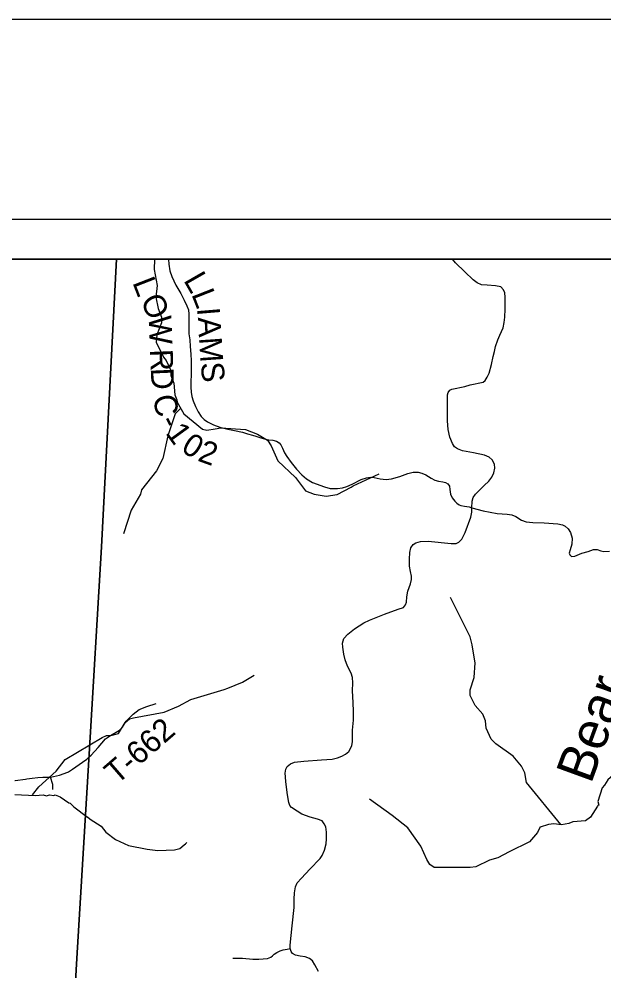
# Model space of a CAD drawing. Extents: x -1.8 to 75.7, y -2 to 25.
# Drawn here: x 6.244 to 7.704, y 19.123 to 21.5 of the extents above; entities that cross this region are included whole.
import ezdxf

# ---------------------------------------------------------------- set-up
doc = ezdxf.new("R2010")
doc.units = 0
for name, color, linetype in [('GM_X_County_Road', 7, 'Continuous'), ('GM_X_County_Road_Text', 7, 'Continuous'), ('GM_X_Minor_River', 7, 'Continuous'), ('GM_X_Minor_River_Text', 7, 'Continuous'), ('GM_X_Township', 7, 'Continuous'), ('GM_X_Township_Road', 7, 'Continuous'), ('GM_X_Township_Road_Text', 7, 'Continuous'), ('GM_X_Township_ROW', 7, 'Continuous'), ('SH_Border', 7, 'Continuous'), ('SH_Data', 7, 'Continuous')]:
    doc.layers.add(name, color=color, linetype=linetype)

msp = doc.modelspace()

# ---------------------------------------------------------------- linework, layer by layer
at = {"layer": 'GM_X_County_Road'}
for points in [[(6.6168, 20.9), (6.6167, 20.8997), (6.6179, 20.8877), (6.6203, 20.8713), (6.6251, 20.8569), (6.6355, 20.8357), (6.6479, 20.8148), (6.6564, 20.7979), (6.6629, 20.7838), (6.6669, 20.7736), (6.668, 20.7626), (6.668, 20.7455), (6.6676, 20.729), (6.6678, 20.7155), (6.668, 20.714)], [(6.9919, 19.1211), (6.9826, 19.1385), (6.9769, 19.148), (6.9692, 19.1539), (6.9581, 19.1577), (6.9457, 19.1598), (6.9339, 19.1623), (6.9264, 19.1668), (6.923, 19.1716), (6.9205, 19.1792), (6.9208, 19.1872), (6.9257, 19.2354), (6.9305, 19.2814), (6.9309, 19.3024), (6.9316, 19.3178), (6.9339, 19.3332), (6.9386, 19.3432), (6.9491, 19.3547), (6.9699, 19.3767), (6.9955, 19.4036), (7.0011, 19.4115), (7.0066, 19.4247), (7.0104, 19.4403), (7.0116, 19.4528), (7.0118, 19.4691), (7.01, 19.4824), (7.0059, 19.4906), (7.0007, 19.4974), (6.9887, 19.5021), (6.9706, 19.5069), (6.95, 19.5146), (6.938, 19.522), (6.9244, 19.5309), (6.9201, 19.5363), (6.9178, 19.5435), (6.9144, 19.5623), (6.9099, 19.5949), (6.909, 19.6074), (6.9083, 19.6169), (6.9098, 19.6266), (6.9135, 19.6334), (6.9217, 19.6398), (6.9319, 19.6443), (6.9547, 19.6466), (6.9989, 19.6504), (7.026, 19.652), (7.0389, 19.6554), (7.0496, 19.6592), (7.0591, 19.6642), (7.067, 19.6706), (7.0706, 19.6764), (7.0747, 19.6857), (7.0763, 19.6952), (7.0768, 19.7054), (7.0768, 19.7244), (7.0786, 19.7489), (7.0788, 19.7704), (7.0777, 19.793), (7.0765, 19.8227), (7.0774, 19.8424), (7.0763, 19.8555), (7.0731, 19.8664), (7.0641, 19.8838), (7.0582, 19.8995), (7.0546, 19.9137), (7.0523, 19.9312), (7.0516, 19.9416), (7.0548, 19.9527), (7.0645, 19.964), (7.0817, 19.9771), (7.1048, 19.9921), (7.1193, 19.9991), (7.1567, 20.0136), (7.1904, 20.0267), (7.204, 20.0306), (7.2088, 20.0369), (7.211, 20.0441), (7.2122, 20.057), (7.2146, 20.0713), (7.2212, 20.0899), (7.2237, 20.1005), (7.2237, 20.1089), (7.2214, 20.1207), (7.2192, 20.1338), (7.2187, 20.1508), (7.2194, 20.1682), (7.2221, 20.1793), (7.228, 20.1881), (7.235, 20.192), (7.2461, 20.1952), (7.2658, 20.1961), (7.3229, 20.1899), (7.3355, 20.1904), (7.3423, 20.1938), (7.3491, 20.2013), (7.3578, 20.218), (7.3723, 20.2563), (7.3745, 20.2682), (7.3743, 20.2791), (7.3755, 20.2959), (7.3779, 20.3051), (7.3833, 20.3131), (7.3915, 20.3211), (7.4053, 20.3347), (7.4167, 20.3458), (7.4245, 20.3558), (7.4298, 20.3665), (7.432, 20.3783), (7.4308, 20.388), (7.4254, 20.3991), (7.4177, 20.4062), (7.4063, 20.4108), (7.3786, 20.4169), (7.3512, 20.4218), (7.3386, 20.4266), (7.3309, 20.4319), (7.3263, 20.4399), (7.3195, 20.4562), (7.3151, 20.4749), (7.3141, 20.4962), (7.3134, 20.5297), (7.3134, 20.5525), (7.3134, 20.5617), (7.3156, 20.5675), (7.3195, 20.5731), (7.3243, 20.5753), (7.3566, 20.5821), (7.3702, 20.5867), (7.4031, 20.593), (7.408, 20.5971), (7.4131, 20.6054), (7.4179, 20.616), (7.4233, 20.6369), (7.4281, 20.657), (7.431, 20.6701), (7.4339, 20.682), (7.4395, 20.699), (7.4446, 20.7104), (7.4529, 20.7291), (7.4555, 20.7419), (7.4572, 20.7557), (7.4575, 20.7754), (7.4575, 20.8052), (7.4565, 20.8166), (7.4534, 20.8239), (7.4468, 20.8309), (7.4339, 20.8336), (7.4131, 20.8353), (7.3985, 20.8365), (7.3874, 20.8414), (7.3774, 20.8484), (7.3568, 20.869), (7.3335, 20.8908), (7.3261, 20.9)], [(6.668, 20.714), (6.6702, 20.6987), (6.6714, 20.682), (6.673, 20.6631), (6.6737, 20.6461), (6.6739, 20.6272), (6.6735, 20.6117), (6.6725, 20.5947), (6.6725, 20.5805), (6.6737, 20.5685), (6.6756, 20.5576), (6.6789, 20.5465), (6.6843, 20.5321), (6.6909, 20.5191), (6.6983, 20.5076), (6.7063, 20.5), (6.7145, 20.4944), (6.7294, 20.4866), (6.745, 20.4809), (6.7648, 20.476), (6.7818, 20.4727), (6.8019, 20.4679), (6.8146, 20.4644), (6.8271, 20.4611), (6.8354, 20.4585), (6.8479, 20.4538), (6.8594, 20.4507), (6.8675, 20.4491), (6.8779, 20.4486), (6.8864, 20.4462), (6.8932, 20.4415), (6.8974, 20.4365), (6.9017, 20.4285), (6.9069, 20.417), (6.9121, 20.4078), (6.9236, 20.3927), (6.9366, 20.3759), (6.9496, 20.3615), (6.9619, 20.3514), (6.9763, 20.3426), (7.0065, 20.3318), (7.0209, 20.3278), (7.0388, 20.3275), (7.0513, 20.3294), (7.0626, 20.3329), (7.0754, 20.3381), (7.0985, 20.3497), (7.1113, 20.3544), (7.1214, 20.3558), (7.1306, 20.3554), (7.1457, 20.3518), (7.1608, 20.3499), (7.1738, 20.3514), (7.1948, 20.358), (7.2149, 20.365), (7.2281, 20.3686), (7.2406, 20.3681), (7.2496, 20.366), (7.2592, 20.3617), (7.2727, 20.3532), (7.2821, 20.3483), (7.2909, 20.3457), (7.3019, 20.3445), (7.3088, 20.3429), (7.3147, 20.3391), (7.3185, 20.3334), (7.3196, 20.3249), (7.3211, 20.3134), (7.3253, 20.3046), (7.3316, 20.2961), (7.3369, 20.2908), (7.3432, 20.2869), (7.3471, 20.2852), (7.3563, 20.2835), (7.3677, 20.2818), (7.3743, 20.2791)]]:
    msp.add_lwpolyline(points, dxfattribs=at)
at = {"layer": 'GM_X_Minor_River'}
for points in [[(6.5816, 20.9), (6.5809, 20.8746), (6.5884, 20.8345), (6.5849, 20.8058), (6.5915, 20.7771), (6.5992, 20.7556), (6.5995, 20.7415), (6.5877, 20.7115), (6.586, 20.693), (6.6041, 20.6556), (6.611, 20.6474), (6.6228, 20.6219), (6.6228, 20.6098), (6.6301, 20.5905), (6.633, 20.5616), (6.6379, 20.5493), (6.6389, 20.5432), (6.655, 20.5142), (6.7015, 20.4762), (6.7128, 20.4736), (6.7336, 20.4764), (6.7473, 20.479), (6.8096, 20.4751), (6.8394, 20.4631), (6.8643, 20.4483), (6.8737, 20.4343), (6.89, 20.3969), (6.9344, 20.3549), (6.9591, 20.3214), (6.9804, 20.3132), (7.0109, 20.3088), (7.0382, 20.3124), (7.0728, 20.3311), (7.0782, 20.3343), (7.143, 20.3642)], [(6.6459, 20.5266), (6.6335, 20.5145), (6.6152, 20.4589), (6.6029, 20.4027), (6.5868, 20.3721), (6.5491, 20.3243), (6.5469, 20.3137), (6.5241, 20.2731), (6.5042, 20.2141)], [(7.5964, 19.4888), (7.5111, 19.5937), (7.5069, 19.6178), (7.4984, 19.6344), (7.4776, 19.659), (7.4343, 19.69), (7.4229, 19.7017), (7.4101, 19.7295), (7.4084, 19.7474), (7.4018, 19.7643), (7.3827, 19.7858), (7.3703, 19.8105), (7.3703, 19.8249), (7.3799, 19.8554), (7.3829, 19.8921), (7.3772, 19.9268), (7.3749, 19.9372), (7.3706, 19.9574), (7.3246, 20.0489), (7.3214, 20.0555)], [(6.2774, 19.5626), (6.2934, 19.5824), (6.3362, 19.6221), (6.359, 19.651), (6.4514, 19.7061), (6.4621, 19.7111), (6.473, 19.7108), (6.4917, 19.7162), (6.5088, 19.743), (6.5197, 19.7522), (6.5292, 19.7549), (6.606, 19.7692), (6.642, 19.7844), (6.6731, 19.8008), (6.7559, 19.8259), (6.765, 19.829), (6.8018, 19.8438), (6.831, 19.8611)], [(7.7329, 19.6164), (7.714, 19.6003), (7.7057, 19.5866), (7.6996, 19.5805), (7.6894, 19.5463), (7.6913, 19.5368), (7.6891, 19.5364), (7.6887, 19.5345), (7.6706, 19.5071), (7.6585, 19.498), (7.6264, 19.4952), (7.6169, 19.491), (7.5984, 19.4876), (7.5791, 19.4906), (7.5663, 19.4886), (7.5447, 19.4821)], [(6.2333, 19.5631), (6.2843, 19.5613), (6.3043, 19.5625), (6.3123, 19.5599), (6.3195, 19.5629), (6.3308, 19.5607), (6.3338, 19.5626), (6.3463, 19.5577), (6.3682, 19.5429), (6.3716, 19.5421), (6.3804, 19.5323), (6.415, 19.5072)], [(7.5454, 19.4823), (7.5388, 19.4682), (7.5181, 19.4453), (7.4678, 19.42), (7.4394, 19.4049), (7.4184, 19.3992), (7.3843, 19.3828), (7.3706, 19.3809), (7.2807, 19.3815), (7.2695, 19.3883), (7.262, 19.4015), (7.2475, 19.4346), (7.2145, 19.4801), (7.1757, 19.5106), (7.1188, 19.5519)], [(6.4148, 19.5073), (6.4212, 19.5016), (6.4492, 19.4842), (6.4602, 19.4694), (6.4844, 19.4508), (6.5173, 19.4364), (6.5638, 19.4266), (6.5899, 19.424), (6.6318, 19.4253), (6.6451, 19.4287), (6.6564, 19.4379), (6.6598, 19.4406), (6.6624, 19.4432)]]:
    msp.add_lwpolyline(points, dxfattribs=at)
at = {"layer": 'GM_X_Township'}
for points in [[(6.4874, 20.9), (2.1, 20.9), (2.1, 17.3659)], [(2.1, 17.3659), (3.1354, 17.3103), (3.6863, 17.2831), (4.4195, 17.2469), (4.6712, 17.2345), (5.2191, 17.2074), (5.4813, 17.1939), (6.252, 17.1543), (6.3199, 17.9861), (6.3212, 18.0078), (6.3226, 18.0577), (6.3233, 18.0805), (6.3259, 18.1065), (6.3299, 18.1515), (6.3889, 19.1678), (6.4185, 19.6642), (6.4493, 20.1816), (6.4874, 20.9)], [(6.4874, 20.9), (6.4493, 20.1816), (6.4185, 19.6642), (6.3889, 19.1678), (6.3299, 18.1515), (6.3259, 18.1065), (6.3233, 18.0805), (6.3226, 18.0577), (6.3212, 18.0078), (6.3199, 17.9861), (6.252, 17.1543), (7.1962, 17.1121), (7.3049, 17.1072), (8.4894, 17.0481), (8.8908, 17.028), (8.9, 17.0276)], [(8.9, 17.0276), (8.9, 20.9), (6.4874, 20.9)]]:
    msp.add_lwpolyline(points, dxfattribs=at)
at = {"layer": 'GM_X_Township_Road'}
for points in [[(7.3743, 20.2791), (7.4024, 20.2719), (7.4378, 20.2648), (7.4631, 20.2639), (7.4747, 20.2619), (7.4847, 20.2576), (7.4985, 20.2483), (7.5098, 20.2445), (7.5268, 20.2425), (7.5547, 20.2421), (7.5891, 20.2394), (7.6008, 20.237), (7.6077, 20.2334), (7.6154, 20.2266), (7.6205, 20.2175), (7.6247, 20.2035), (7.6243, 20.1882), (7.6203, 20.1745), (7.6179, 20.1661), (7.619, 20.1617), (7.6234, 20.1579), (7.6318, 20.1588), (7.6495, 20.1661), (7.6648, 20.1707), (7.6784, 20.1753), (7.6872, 20.1752), (7.6965, 20.1721), (7.7042, 20.1705), (7.7184, 20.171)], [(6.367, 19.6199), (6.3776, 19.6267), (6.4021, 19.6443), (6.4127, 19.6516), (6.418, 19.6565), (6.4239, 19.6619), (6.4412, 19.6812), (6.4596, 19.7021), (6.4719, 19.711), (6.4945, 19.7242), (6.5018, 19.732), (6.5116, 19.7468), (6.5283, 19.7638), (6.5437, 19.7758), (6.5632, 19.7828), (6.5861, 19.7909)], [(6.322, 19.6066), (6.3446, 19.6114), (6.3655, 19.6189), (6.367, 19.6199)], [(6.2328, 19.5986), (6.2343, 19.5988), (6.2595, 19.6017)], [(6.2595, 19.6017), (6.2631, 19.6022), (6.2765, 19.6044), (6.2904, 19.6058), (6.3033, 19.6066), (6.322, 19.6066)], [(6.8956, 19.173), (6.9032, 19.1753), (6.9137, 19.177), (6.9205, 19.1792)]]:
    msp.add_lwpolyline(points, dxfattribs=at)
at = {"layer": 'GM_X_Township_ROW'}
for points in [[(6.3284, 19.5759), (6.3279, 19.5888), (6.322, 19.6066)], [(6.7779, 19.155), (6.8014, 19.155), (6.8273, 19.1525), (6.8424, 19.1525), (6.8644, 19.1541), (6.8725, 19.1571), (6.8766, 19.1602), (6.8811, 19.165), (6.8877, 19.1693), (6.8954, 19.1729), (6.8956, 19.173)]]:
    msp.add_lwpolyline(points, dxfattribs=at)
at = {"layer": 'SH_Border'}
msp.add_lwpolyline([(1.5, 21.5), (33.5, 21.5), (33.5, 0.5), (1.5, 0.5)], close=True, dxfattribs=at)
at = {"layer": 'SH_Data'}
for p, q in [((2, 21), (9, 21)), ((2.1, 20.9), (8.9, 20.9))]:
    msp.add_line(p, q, dxfattribs=at)

# ---------------------------------------------------------------- texts
at = {"layer": 'GM_X_County_Road_Text'}
for s, rotation, p in [('L', 291.2729, (6.5263, 20.8422)), ('L', 299.8274, (6.6534, 20.8478)), ('L', 291.4457, (6.6736, 20.8129)), ('O', 298.5018, (6.545, 20.7955)), ('W', 272.4964, (6.5671, 20.7581)), ('I', 274.7828, (6.6882, 20.7776)), ('A', 273.1818, (6.6901, 20.7548)), ('M', 273.9872, (6.6929, 20.704)), ('R', 272.303, (6.5706, 20.6747)), ('S', 275.1606, (6.6973, 20.6412)), ('D', 272.4218, (6.5725, 20.628)), ('C', 282.5703, (6.5769, 20.5559)), ('-', 296.9471, (6.5923, 20.4957)), ('1', 305.93, (6.6079, 20.4666)), ('0', 327.6164, (6.6455, 20.4223)), ('2', 340.2531, (6.6873, 20.3976))]:
    msp.add_text(s, height=0.0568, rotation=rotation, dxfattribs=at).set_placement(p)
at = {"layer": 'GM_X_Minor_River_Text'}
msp.add_text('Bear', height=0.0947, rotation=69.9999, dxfattribs=at).set_placement((7.6719, 19.5877))
at = {"layer": 'GM_X_Township_Road_Text'}
msp.add_text('T-662', height=0.05682, rotation=40.9289, dxfattribs=at).set_placement((6.4879, 19.5868))

doc.saveas('drawing.dxf')
